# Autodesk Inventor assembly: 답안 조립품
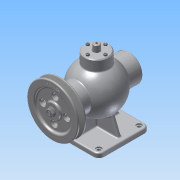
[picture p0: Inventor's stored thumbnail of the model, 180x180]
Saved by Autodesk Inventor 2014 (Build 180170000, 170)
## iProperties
Created: 2017-01
Part Number: 답안 조립품
Document SubType Name: Assembly
Designer: ksu
Author: ksu
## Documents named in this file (17)
- C:\Users\ksu\Desktop\470118V1016\답안 조립품.iam
- C:\Users\ksu\Desktop\470118V1016\1 본체.ipt
- C:\Users\ksu\Desktop\470118V1016 (2)\V-벨트풀리.ipt
- C:\Users\ksu\Desktop\470118V1016 (2)\너트 M8.ipt
- C:\Users\ksu\Desktop\470118V1016 (2)\뒤커버.ipt
- C:\Users\ksu\Desktop\470118V1016 (2)\멈춤링- 15 x 1.ipt
- C:\Users\ksu\Desktop\470118V1016 (2)\멈춤링- 35x1.6.ipt
- C:\Users\ksu\Desktop\470118V1016 (2)\베어링- 6202.ipt
- C:\Users\ksu\Desktop\470118V1016 (2)\볼트 M4 x 12.ipt
- C:\Users\ksu\Desktop\470118V1016 (2)\볼트 M4 x 16.ipt
- C:\Users\ksu\Desktop\470118V1016 (2)\부시.ipt
- C:\Users\ksu\Desktop\470118V1016 (2)\상부커버.ipt
- C:\Users\ksu\Desktop\470118V1016 (2)\슬라이드.ipt
- C:\Users\ksu\Desktop\470118V1016 (2)\앞커버.ipt
- C:\Users\ksu\Desktop\470118V1016 (2)\오일실 15 30 7.ipt
- C:\Users\ksu\Desktop\470118V1016 (2)\키 4 x 4 x 12.ipt
- C:\Users\ksu\Desktop\470118V1016 (2)\편심축.ipt
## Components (17 placed, 6 different names)
1. 1 본체:1 — Mate:1, Mate:2, Mate:3, Mate:17, Mate:18, Mate:19, Mate:48, Mate:49, Mate:51
2. V-벨트풀리:1 — Mate:42, Mate:43, Mate:44, Mate:45, Mate:47
3. KS B 1336 - 35x1.6:1 — Mate:40, Mate:41
4. KS B 2023 - 6202 - 15 x 35 x 11 - 7.8:1 — Mate:30, Mate:33, Mate:34, Mate:35
5. KS B 1021 - 에 따름 ISO 1207 - 미터 A  M 4 x 12:1 — Mate:53, Mate:58
6. ISO 4762 M4 x 16:1 — Mate:4, Mate:5
7. ISO 4762 M4 x 16:2 — Mate:10, Mate:11
8. ISO 4762 M4 x 16:3 — Mate:8, Mate:9
9. ISO 4762 M4 x 16:4 — Mate:6, Mate:7
10. ISO 4762 M4 x 16:5 — Mate:20, Mate:21
11. ISO 4762 M4 x 16:6 — Mate:22, Mate:23
12. ISO 4762 M4 x 16:7 — Mate:26, Mate:27
13. ISO 4762 M4 x 16:8 — Mate:24, Mate:25
14. KS B 2023 - 6202 - 15 x 35 x 11 - 7.8:2 — Mate:31, Mate:32, Mate:39, Mate:41
15. KS B 1021 - 에 따름 ISO 1207 - 미터 A  M 4 x 12:2 — Mate:52, Mate:59
16. KS B 1021 - 에 따름 ISO 1207 - 미터 A  M 4 x 12:3 — Mate:54, Mate:56
17. KS B 1021 - 에 따름 ISO 1207 - 미터 A  M 4 x 12:4 — Mate:55, Mate:57
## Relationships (47: Mate 47)
- Mate:1: 1 본체:1
- Mate:2: 1 본체:1
- Mate:3: 1 본체:1
- Mate:4: ISO 4762 M4 x 16:1
- Mate:5: ISO 4762 M4 x 16:1
- Mate:6: ISO 4762 M4 x 16:4
- Mate:7: ISO 4762 M4 x 16:4
- Mate:8: ISO 4762 M4 x 16:3
- Mate:9: ISO 4762 M4 x 16:3
- Mate:10: ISO 4762 M4 x 16:2
- Mate:11: ISO 4762 M4 x 16:2
- Mate:17: 1 본체:1
- Mate:18: 1 본체:1
- Mate:19: 1 본체:1
- Mate:20: ISO 4762 M4 x 16:5
- Mate:21: ISO 4762 M4 x 16:5
- Mate:22: ISO 4762 M4 x 16:6
- Mate:23: ISO 4762 M4 x 16:6
- Mate:24: ISO 4762 M4 x 16:8
- Mate:25: ISO 4762 M4 x 16:8
- Mate:26: ISO 4762 M4 x 16:7
- Mate:27: ISO 4762 M4 x 16:7
- Mate:30: KS B 2023 - 6202 - 15 x 35 x 11 - 7.8:1
- Mate:31: KS B 2023 - 6202 - 15 x 35 x 11 - 7.8:2
- Mate:32: KS B 2023 - 6202 - 15 x 35 x 11 - 7.8:2
- Mate:33: KS B 2023 - 6202 - 15 x 35 x 11 - 7.8:1
- Mate:34: KS B 2023 - 6202 - 15 x 35 x 11 - 7.8:1
- Mate:35: KS B 2023 - 6202 - 15 x 35 x 11 - 7.8:1
- Mate:39: KS B 2023 - 6202 - 15 x 35 x 11 - 7.8:2
- Mate:40: KS B 1336 - 35x1.6:1
- Mate:41: KS B 1336 - 35x1.6:1 ↔ KS B 2023 - 6202 - 15 x 35 x 11 - 7.8:2
- Mate:42: V-벨트풀리:1
- Mate:43: V-벨트풀리:1
- Mate:44: V-벨트풀리:1
- Mate:45: V-벨트풀리:1
- Mate:47: V-벨트풀리:1
- Mate:48: 1 본체:1
- Mate:49: 1 본체:1
- Mate:51: 1 본체:1
- Mate:52: KS B 1021 - 에 따름 ISO 1207 - 미터 A  M 4 x 12:2
- Mate:53: KS B 1021 - 에 따름 ISO 1207 - 미터 A  M 4 x 12:1
- Mate:54: KS B 1021 - 에 따름 ISO 1207 - 미터 A  M 4 x 12:3
- Mate:55: KS B 1021 - 에 따름 ISO 1207 - 미터 A  M 4 x 12:4
- Mate:56: KS B 1021 - 에 따름 ISO 1207 - 미터 A  M 4 x 12:3
- Mate:57: KS B 1021 - 에 따름 ISO 1207 - 미터 A  M 4 x 12:4
- Mate:58: KS B 1021 - 에 따름 ISO 1207 - 미터 A  M 4 x 12:1
- Mate:59: KS B 1021 - 에 따름 ISO 1207 - 미터 A  M 4 x 12:2
